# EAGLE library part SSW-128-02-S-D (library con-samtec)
THROUGH-HOLE .025" SQ POST SOCKET Source: Samtec SSW.pdf
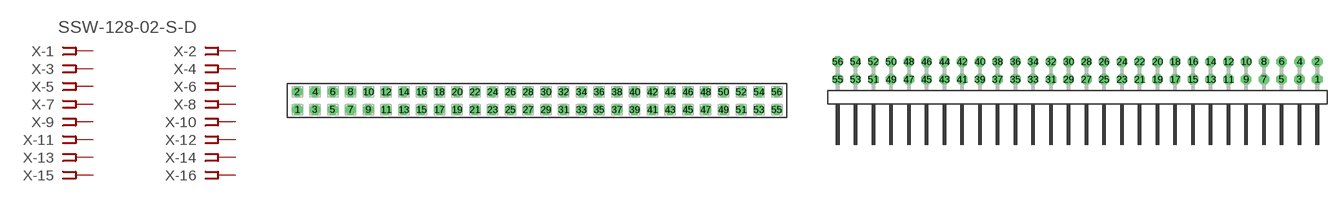
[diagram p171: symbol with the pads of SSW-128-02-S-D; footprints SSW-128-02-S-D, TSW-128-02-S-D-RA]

Designator prefix X; gates -1=FPINV -2=FPIN -3=FPIN -4=FPIN -5=FPIN -6=FPIN -7=FPIN -8=FPIN -9=FPIN -10=FPIN -11=FPIN -12=FPIN -13=FPIN -14=FPIN -15=FPIN -16=FPIN -17=FPIN -18=FPIN -19=FPIN -20=FPIN -21=FPIN -22=FPIN -23=FPIN -24=FPIN -25=FPIN -26=FPIN -27=FPIN -28=FPIN -29=FPIN -30=FPIN -31=FPIN -32=FPIN -33=FPIN -34=FPIN -35=FPIN -36=FPIN -37=FPIN -38=FPIN -39=FPIN -40=FPIN -41=FPIN -42=FPIN -43=FPIN -44=FPIN -45=FPIN -46=FPIN -47=FPIN -48=FPIN -49=FPIN -50=FPIN -51=FPIN -52=FPIN -53=FPIN -54=FPIN -55=FPIN -56=FPIN

## SSW-128-02-S-D (MPN: SSW-128-02-S-D; OC_FARNELL: unknown; OC_NEWARK: 11P9773)  [SSW-128-02-S-D]
1  -1:1  pas
2  -2:1  pas
3  -3:1  pas
4  -4:1  pas
5  -5:1  pas
6  -6:1  pas
7  -7:1  pas
8  -8:1  pas
9  -9:1  pas
10  -10:1  pas
11  -11:1  pas
12  -12:1  pas
13  -13:1  pas
14  -14:1  pas
15  -15:1  pas
16  -16:1  pas
17  -17:1  pas
18  -18:1  pas
19  -19:1  pas
20  -20:1  pas
21  -21:1  pas
22  -22:1  pas
23  -23:1  pas
24  -24:1  pas
25  -25:1  pas
26  -26:1  pas
27  -27:1  pas
28  -28:1  pas
29  -29:1  pas
30  -30:1  pas
31  -31:1  pas
32  -32:1  pas
33  -33:1  pas
34  -34:1  pas
35  -35:1  pas
36  -36:1  pas
37  -37:1  pas
38  -38:1  pas
39  -39:1  pas
40  -40:1  pas
41  -41:1  pas
42  -42:1  pas
43  -43:1  pas
44  -44:1  pas
45  -45:1  pas
46  -46:1  pas
47  -47:1  pas
48  -48:1  pas
49  -49:1  pas
50  -50:1  pas
51  -51:1  pas
52  -52:1  pas
53  -53:1  pas
54  -54:1  pas
55  -55:1  pas
56  -56:1  pas

## SSW-128-02-S-D-RA (MPN: SSW-128-02-S-D-RA; OC_FARNELL: unknown; OC_NEWARK: 11P9774)  [TSW-128-02-S-D-RA]
Pads as for SSW-128-02-S-D

## Footprint SSW-128-02-S-D (pad centres in mm)
THROUGH-HOLE .025" SQ POST SOCKET Source: Samtec SSW.pdf
drill 1 pad 1.5 octagon: 1 -34.29,-1.27; 2 -34.29,1.27; 3 -31.75,-1.27; 4 -31.75,1.27; 5 -29.21,-1.27; 6 -29.21,1.27; 7 -26.67,-1.27; 8 -26.67,1.27; 9 -24.13,-1.27; 10 -24.13,1.27; 11 -21.59,-1.27; 12 -21.59,1.27; 13 -19.05,-1.27; 14 -19.05,1.27; 15 -16.51,-1.27; 16 -16.51,1.27; 17 -13.97,-1.27; 18 -13.97,1.27; 19 -11.43,-1.27; 20 -11.43,1.27; 21 -8.89,-1.27; 22 -8.89,1.27; 23 -6.35,-1.27; 24 -6.35,1.27; 25 -3.81,-1.27; 26 -3.81,1.27; 27 -1.27,-1.27; 28 -1.27,1.27; 29 1.27,-1.27; 30 1.27,1.27; 31 3.81,-1.27; 32 3.81,1.27; 33 6.35,-1.27; 34 6.35,1.27; 35 8.89,-1.27; 36 8.89,1.27; 37 11.43,-1.27; 38 11.43,1.27; 39 13.97,-1.27; 40 13.97,1.27; 41 16.51,-1.27; 42 16.51,1.27; 43 19.05,-1.27; 44 19.05,1.27; 45 21.59,-1.27; 46 21.59,1.27; 47 24.13,-1.27; 48 24.13,1.27; 49 26.67,-1.27; 50 26.67,1.27; 51 29.21,-1.27; 52 29.21,1.27; 53 31.75,-1.27; 54 31.75,1.27; 55 34.29,-1.27; 56 34.29,1.27

## Footprint TSW-128-02-S-D-RA (pad centres in mm)
THROUGH-HOLE .025" SQ POST HEADER Source: Samtec TSW.pdf
drill 1 pad 1.5 octagon: 1 34.29,1.524; 2 34.29,4.064; 3 31.75,1.524; 4 31.75,4.064; 5 29.21,1.524; 6 29.21,4.064; 7 26.67,1.524; 8 26.67,4.064; 9 24.13,1.524; 10 24.13,4.064; 11 21.59,1.524; 12 21.59,4.064; 13 19.05,1.524; 14 19.05,4.064; 15 16.51,1.524; 16 16.51,4.064; 17 13.97,1.524; 18 13.97,4.064; 19 11.43,1.524; 20 11.43,4.064; 21 8.89,1.524; 22 8.89,4.064; 23 6.35,1.524; 24 6.35,4.064; 25 3.81,1.524; 26 3.81,4.064; 27 1.27,1.524; 28 1.27,4.064; 29 -1.27,1.524; 30 -1.27,4.064; 31 -3.81,1.524; 32 -3.81,4.064; 33 -6.35,1.524; 34 -6.35,4.064; 35 -8.89,1.524; 36 -8.89,4.064; 37 -11.43,1.524; 38 -11.43,4.064; 39 -13.97,1.524; 40 -13.97,4.064; 41 -16.51,1.524; 42 -16.51,4.064; 43 -19.05,1.524; 44 -19.05,4.064; 45 -21.59,1.524; 46 -21.59,4.064; 47 -24.13,1.524; 48 -24.13,4.064; 49 -26.67,1.524; 50 -26.67,4.064; 51 -29.21,1.524; 52 -29.21,4.064; 53 -31.75,1.524; 54 -31.75,4.064; 55 -34.29,1.524; 56 -34.29,4.064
